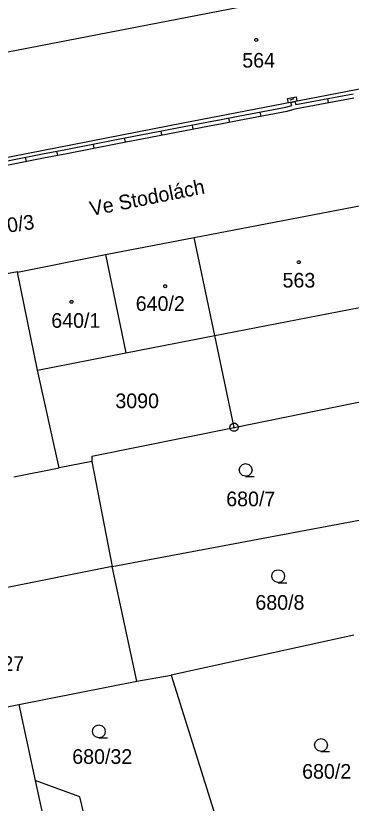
# Model space of a CAD drawing. Extents: x -777309 to -774195, y -1144706 to -1143600.
# Drawn here: x -774490.6 to -774451.7, y -1144589.5 to -1144498.1 of the extents above; entities that cross this region are included whole.
import ezdxf

# ---------------------------------------------------------------- set-up
doc = ezdxf.new("R2010")
doc.units = 0
for name, color, linetype in [('1', 7, 'Continuous'), ('12', 7, 'Continuous'), ('13', 7, 'Continuous'), ('2', 7, 'Continuous'), ('3', 7, 'Continuous'), ('4', 7, 'Continuous'), ('5', 7, 'Continuous'), ('7', 7, 'Continuous'), ('8', 7, 'Continuous')]:
    doc.layers.add(name, color=color, linetype=linetype)

msp = doc.modelspace()

# ---------------------------------------------------------------- linework, layer by layer
at = {"layer": '1'}
for p, q in [((-774431.47, -1144502.88), (-774452.35, -1144506.93)), ((-774452.35, -1144506.93), (-774471.21, -1144510.59)), ((-774471.21, -1144510.59), (-774498.59, -1144515.91)), ((-774469.95, -1144523.84), (-774449.27, -1144519.87)), ((-774480.22, -1144525.82), (-774469.95, -1144523.84)), ((-774467.55, -1144535.22), (-774469.95, -1144523.84)), ((-774490.41, -1144527.88), (-774480.22, -1144525.82)), ((-774480.22, -1144525.82), (-774477.87, -1144537.23)), ((-774504.68, -1144530.51), (-774490.43, -1144527.78)), ((-774490.43, -1144527.78), (-774490.41, -1144527.88)), ((-774488.1, -1144539.22), (-774490.41, -1144527.88)), ((-774467.55, -1144535.22), (-774446.89, -1144531.2)), ((-774477.87, -1144537.23), (-774467.55, -1144535.22)), ((-774465.3, -1144545.87), (-774467.55, -1144535.22)), ((-774488.1, -1144539.22), (-774477.87, -1144537.23)), ((-774485.57, -1144550.57), (-774488.1, -1144539.22)), ((-774465.3, -1144545.87), (-774448.29, -1144542.43)), ((-774481.82, -1144549.21), (-774465.3, -1144545.87)), ((-774481.79, -1144549.82), (-774485.57, -1144550.57)), ((-774481.82, -1144549.21), (-774481.79, -1144549.82)), ((-774481.79, -1144549.82), (-774479.43, -1144562)), ((-774490.84, -1144551.61), (-774485.57, -1144550.57)), ((-774479.43, -1144562), (-774448.82, -1144556.24)), ((-774479.43, -1144562), (-774511.58, -1144568.49)), ((-774476.58, -1144575.31), (-774479.43, -1144562)), ((-774451.44, -1144569.98), (-774472.62, -1144574.63)), ((-774476.58, -1144575.31), (-774472.62, -1144574.63)), ((-774472.62, -1144574.63), (-774465.1, -1144598.47)), ((-774490.28, -1144578.03), (-774476.58, -1144575.31)), ((-774502.21, -1144580.4), (-774490.28, -1144578.03)), ((-774490.28, -1144578.03), (-774488.37, -1144586.85)), ((-774483.2, -1144588.74), (-774488.37, -1144586.85)), ((-774488.37, -1144586.85), (-774487.02, -1144593.11)), ((-774481.81, -1144594.54), (-774483.2, -1144588.74))]:
    msp.add_line(p, q, dxfattribs=at)
at = {"layer": '12'}
for p, q in [((-774498.02, -1144503.54), (-774454.77, -1144495.17)), ((-774431.47, -1144502.88), (-774452.35, -1144506.93)), ((-774452.35, -1144506.93), (-774471.21, -1144510.59)), ((-774471.21, -1144510.59), (-774498.59, -1144515.91)), ((-774469.95, -1144523.84), (-774449.27, -1144519.87)), ((-774480.22, -1144525.82), (-774469.95, -1144523.84)), ((-774467.55, -1144535.22), (-774469.95, -1144523.84)), ((-774467.55, -1144535.22), (-774469.95, -1144523.84)), ((-774490.41, -1144527.88), (-774480.22, -1144525.82)), ((-774480.22, -1144525.82), (-774477.87, -1144537.23)), ((-774480.22, -1144525.82), (-774477.87, -1144537.23)), ((-774504.68, -1144530.51), (-774490.43, -1144527.78)), ((-774490.43, -1144527.78), (-774490.41, -1144527.88)), ((-774488.1, -1144539.22), (-774490.41, -1144527.88)), ((-774488.1, -1144539.22), (-774490.41, -1144527.88)), ((-774467.55, -1144535.22), (-774446.89, -1144531.2)), ((-774477.87, -1144537.23), (-774467.55, -1144535.22)), ((-774488.1, -1144539.22), (-774477.87, -1144537.23)), ((-774485.57, -1144550.57), (-774488.1, -1144539.22)), ((-774490.84, -1144551.61), (-774485.57, -1144550.57))]:
    msp.add_line(p, q, dxfattribs=at)
at = {"layer": '13'}
for p, q in [((-774458.378, -1144507.755), (-774458.848, -1144507.926)), ((-774454.347, -1144508.21), (-774454.44, -1144507.718)), ((-774462.185, -1144509.79), (-774462.28, -1144509.299)), ((-774465.948, -1144510.002), (-774465.85, -1144510.492)), ((-774473.809, -1144511.485), (-774473.716, -1144511.976)), ((-774470.044, -1144511.285), (-774470.138, -1144510.794)), ((-774477.903, -1144512.782), (-774477.997, -1144512.29)), ((-774481.663, -1144513.007), (-774481.565, -1144513.498)), ((-774485.75, -1144514.337), (-774485.843, -1144513.845)), ((-774489.515, -1144514.537), (-774489.42, -1144515.028))]:
    msp.add_line(p, q, dxfattribs=at)
for points in [[(-774491.76, -1144514.97), (-774487.51, -1144514.15), (-774484.81, -1144513.64), (-774478.94, -1144512.46), (-774468.26, -1144510.43), (-774466.79, -1144510.17), (-774464.84, -1144509.78), (-774459.33, -1144508.74), (-774458.63, -1144508.53), (-774458.75, -1144508.17), (-774458.26, -1144508.08), (-774458.14, -1144508.41), (-774451.51, -1144507.16)], [(-774451.41, -1144507.66), (-774458.25, -1144508.94), (-774459.21, -1144509.22), (-774464.74, -1144510.28), (-774466.69, -1144510.67), (-774468.18, -1144510.93), (-774478.84, -1144512.96), (-774484.71, -1144514.14), (-774487.41, -1144514.65), (-774491.66, -1144515.47)]]:
    msp.add_lwpolyline(points, dxfattribs=at)
msp.add_lwpolyline([(-774459.1, -1144507.73), (-774458.12, -1144507.54), (-774458.02, -1144508.03), (-774459.01, -1144508.22)], close=True, dxfattribs=at)
at = {"layer": '3'}
for points in [[(-774463.96, -1144551.55), (-774464.34, -1144551.45), (-774464.61, -1144551.18), (-774464.71, -1144550.81), (-774464.61, -1144550.44), (-774464.34, -1144550.17), (-774463.97, -1144550.07), (-774463.6, -1144550.17), (-774463.33, -1144550.44), (-774463.23, -1144550.82), (-774463.33, -1144551.2), (-774463.6, -1144551.47), (-774463.98, -1144551.57), (-774462.98, -1144551.57)], [(-774460.19, -1144563.87), (-774460.57, -1144563.77), (-774460.84, -1144563.5), (-774460.94, -1144563.13), (-774460.84, -1144562.76), (-774460.57, -1144562.49), (-774460.2, -1144562.39), (-774459.83, -1144562.49), (-774459.56, -1144562.76), (-774459.46, -1144563.14), (-774459.56, -1144563.52), (-774459.83, -1144563.79), (-774460.21, -1144563.89), (-774459.21, -1144563.89)], [(-774480.98, -1144581.88), (-774481.36, -1144581.78), (-774481.63, -1144581.51), (-774481.73, -1144581.14), (-774481.63, -1144580.77), (-774481.36, -1144580.5), (-774480.99, -1144580.4), (-774480.62, -1144580.5), (-774480.35, -1144580.77), (-774480.25, -1144581.15), (-774480.35, -1144581.53), (-774480.62, -1144581.8), (-774481, -1144581.9), (-774480, -1144581.9)], [(-774455.22, -1144583.46), (-774455.6, -1144583.36), (-774455.87, -1144583.09), (-774455.97, -1144582.72), (-774455.87, -1144582.35), (-774455.6, -1144582.08), (-774455.23, -1144581.98), (-774454.86, -1144582.08), (-774454.59, -1144582.35), (-774454.49, -1144582.73), (-774454.59, -1144583.11), (-774454.86, -1144583.38), (-774455.24, -1144583.48), (-774454.24, -1144583.48)]]:
    msp.add_lwpolyline(points, dxfattribs=at)
at = {"layer": '4'}
msp.add_line((-774498.02, -1144503.54), (-774454.77, -1144495.17), dxfattribs=at)
at = {"layer": '5'}
for points in [[(-774462.74, -1144500.75), (-774462.64, -1144500.77), (-774462.59, -1144500.86), (-774462.57, -1144500.92), (-774462.59, -1144501.01), (-774462.67, -1144501.08), (-774462.74, -1144501.09), (-774462.83, -1144501.06), (-774462.89, -1144501), (-774462.91, -1144500.92), (-774462.89, -1144500.83), (-774462.81, -1144500.76)], [(-774457.81, -1144526.53), (-774457.71, -1144526.55), (-774457.66, -1144526.64), (-774457.64, -1144526.7), (-774457.66, -1144526.79), (-774457.74, -1144526.86), (-774457.81, -1144526.87), (-774457.9, -1144526.84), (-774457.96, -1144526.78), (-774457.98, -1144526.7), (-774457.96, -1144526.61), (-774457.88, -1144526.54)], [(-774473.3, -1144529.33), (-774473.2, -1144529.35), (-774473.15, -1144529.44), (-774473.13, -1144529.5), (-774473.15, -1144529.59), (-774473.23, -1144529.66), (-774473.3, -1144529.67), (-774473.39, -1144529.64), (-774473.45, -1144529.58), (-774473.47, -1144529.5), (-774473.45, -1144529.41), (-774473.37, -1144529.34)], [(-774484.15, -1144531.14), (-774484.05, -1144531.16), (-774484, -1144531.25), (-774483.98, -1144531.31), (-774484, -1144531.4), (-774484.08, -1144531.47), (-774484.15, -1144531.48), (-774484.24, -1144531.45), (-774484.3, -1144531.39), (-774484.32, -1144531.31), (-774484.3, -1144531.22), (-774484.22, -1144531.15)]]:
    msp.add_lwpolyline(points, close=True, dxfattribs=at)
at = {"layer": '8'}
msp.add_line((-774465.42, -1144545.87), (-774465.18, -1144545.87), dxfattribs=at)
msp.add_lwpolyline([(-774465.15, -1144545.39), (-774464.9, -1144545.57), (-774464.8, -1144545.86), (-774464.9, -1144546.15), (-774465.15, -1144546.33), (-774465.46, -1144546.33), (-774465.71, -1144546.15), (-774465.81, -1144545.86), (-774465.71, -1144545.57), (-774465.46, -1144545.39)], close=True, dxfattribs=at)

# ---------------------------------------------------------------- texts
at = {"layer": '2'}
for s, p in [('564', (-774464.363, -1144504.13)), ('563', (-774459.693, -1144529.65)), ('640/2', (-774476.713, -1144532.36)), ('640/1', (-774486.503, -1144534.32)), ('3090', (-774479.074, -1144543.64)), ('680/7', (-774466.223, -1144555.02)), ('680/8', (-774462.843, -1144567.03)), ('680/27', (-774496.603, -1144574.12)), ('680/32', (-774484.073, -1144584.91)), ('680/2', (-774457.423, -1144586.63))]:
    msp.add_text(s, height=1.7, dxfattribs=at).set_placement(p)
msp.add_text('680/3', height=1.7, rotation=8.0787, dxfattribs=at).set_placement((-774494.007, -1144523.64))
at = {"layer": '7'}
msp.add_text('Ve Stodolách', height=1.7, rotation=11.22997, dxfattribs=at).set_placement((-774481.867, -1144521.36))

doc.saveas('drawing.dxf')
